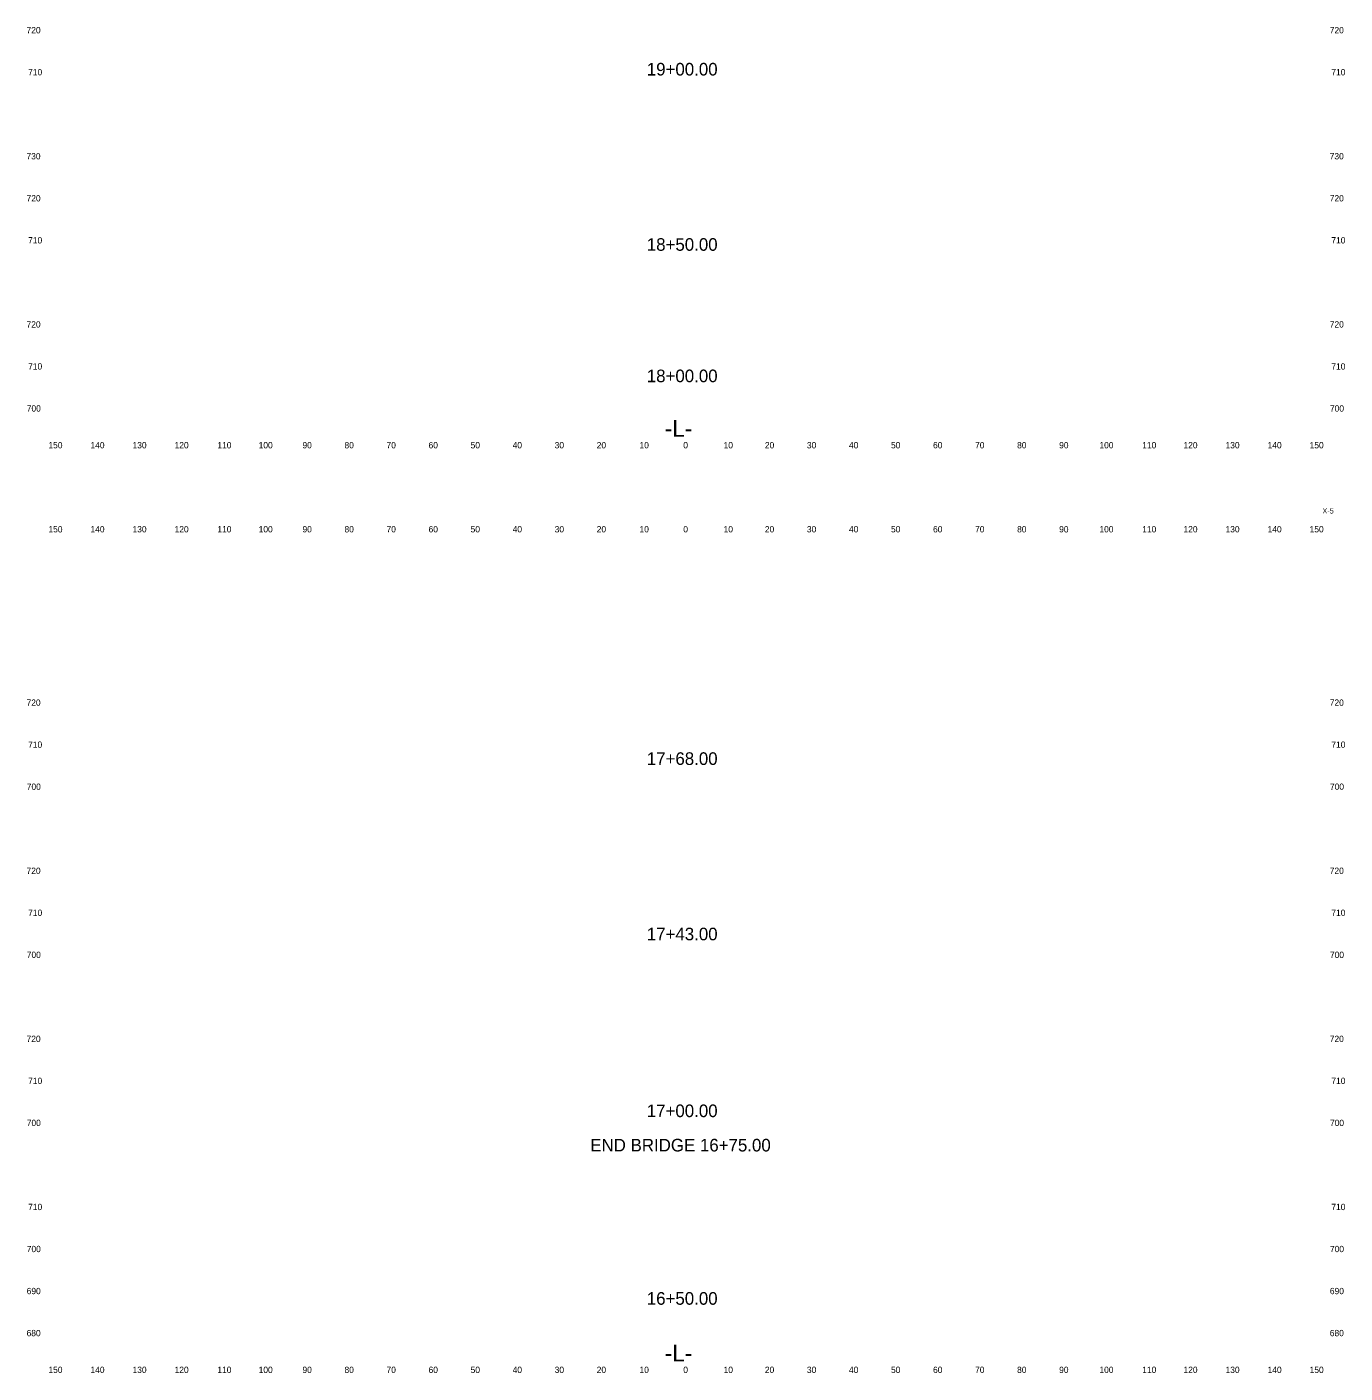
# Model space of a CAD drawing. Extents: x 3 to 317, y 1 to 1307.
# Drawn here: x 3.3 to 316.9, y 661.2 to 981.5 of the extents above; entities that cross this region are included whole.
import ezdxf

# ---------------------------------------------------------------- set-up
doc = ezdxf.new("R2010")
doc.units = 0
for name, color, linetype in [('Prop XS Alignment Label', 7, 'Continuous'), ('Prop XS Elevation Labels', 7, 'Continuous'), ('Prop XS Offset Labels', 7, 'Continuous'), ('Prop XS Sheet Number', 7, 'Continuous'), ('Prop XS Station Labels', 7, 'Continuous')]:
    doc.layers.add(name, color=color, linetype=linetype)

msp = doc.modelspace()

# ---------------------------------------------------------------- texts
at = {"layer": 'Prop XS Alignment Label'}
for p in [(155.06, 884), (155.06, 664)]:
    msp.add_text('-L-', height=4, dxfattribs=at).set_placement(p)
at = {"layer": 'Prop XS Elevation Labels'}
for s, p in [('720', (3.23, 980)), ('720', (313.23, 980)), ('710', (3.61, 970)), ('710', (313.61, 970)), ('730', (3.22, 950)), ('730', (313.22, 950)), ('720', (3.23, 940)), ('720', (313.23, 940)), ('710', (3.61, 930)), ('710', (313.61, 930)), ('720', (3.23, 910)), ('720', (313.23, 910)), ('710', (3.61, 900)), ('710', (313.61, 900)), ('700', (3.28, 890)), ('700', (313.28, 890)), ('720', (3.23, 820)), ('720', (313.23, 820)), ('710', (3.61, 810)), ('710', (313.61, 810)), ('700', (3.28, 800)), ('700', (313.28, 800)), ('720', (3.23, 780)), ('720', (313.23, 780)), ('710', (3.61, 770)), ('710', (313.61, 770)), ('700', (3.28, 760)), ('700', (313.28, 760)), ('720', (3.23, 740)), ('720', (313.23, 740)), ('710', (3.61, 730)), ('710', (313.61, 730)), ('700', (3.28, 720)), ('700', (313.28, 720)), ('710', (3.61, 700)), ('710', (313.61, 700)), ('700', (3.28, 690)), ('700', (313.28, 690)), ('690', (3.26, 680)), ('690', (313.26, 680)), ('680', (3.24, 670)), ('680', (313.24, 670))]:
    msp.add_text(s, height=1.5, dxfattribs=at).set_placement(p)
at = {"layer": 'Prop XS Offset Labels'}
for s, p in [('150', (8.44, 881.25)), ('140', (18.44, 881.25)), ('130', (28.44, 881.25)), ('120', (38.44, 881.25)), ('110', (48.62, 881.25)), ('100', (58.44, 881.25)), ('90', (68.86, 881.25)), ('80', (78.86, 881.25)), ('70', (88.86, 881.25)), ('60', (98.86, 881.25)), ('50', (108.86, 881.25)), ('40', (118.86, 881.25)), ('30', (128.86, 881.25)), ('20', (138.86, 881.25)), ('10', (149.04, 881.25)), ('0', (159.45, 881.25)), ('0', (159.45, 881.25)), ('10', (169.04, 881.25)), ('20', (178.86, 881.25)), ('30', (188.86, 881.25)), ('40', (198.86, 881.25)), ('50', (208.86, 881.25)), ('60', (218.86, 881.25)), ('70', (228.86, 881.25)), ('80', (238.86, 881.25)), ('90', (248.86, 881.25)), ('100', (258.44, 881.25)), ('110', (268.62, 881.25)), ('120', (278.44, 881.25)), ('130', (288.44, 881.25)), ('140', (298.44, 881.25)), ('150', (308.44, 881.25)), ('150', (8.44, 861.25)), ('140', (18.44, 861.25)), ('130', (28.44, 861.25)), ('120', (38.44, 861.25)), ('110', (48.62, 861.25)), ('100', (58.44, 861.25)), ('90', (68.86, 861.25)), ('80', (78.86, 861.25)), ('70', (88.86, 861.25)), ('60', (98.86, 861.25)), ('50', (108.86, 861.25)), ('40', (118.86, 861.25)), ('30', (128.86, 861.25)), ('20', (138.86, 861.25)), ('10', (149.04, 861.25)), ('0', (159.45, 861.25)), ('0', (159.45, 861.25)), ('10', (169.04, 861.25)), ('20', (178.86, 861.25)), ('30', (188.86, 861.25)), ('40', (198.86, 861.25)), ('50', (208.86, 861.25)), ('60', (218.86, 861.25)), ('70', (228.86, 861.25)), ('80', (238.86, 861.25)), ('90', (248.86, 861.25)), ('100', (258.44, 861.25)), ('110', (268.62, 861.25)), ('120', (278.44, 861.25)), ('130', (288.44, 861.25)), ('140', (298.44, 861.25)), ('150', (308.44, 861.25)), ('150', (8.44, 661.25)), ('140', (18.44, 661.25)), ('130', (28.44, 661.25)), ('120', (38.44, 661.25)), ('110', (48.62, 661.25)), ('100', (58.44, 661.25)), ('90', (68.86, 661.25)), ('80', (78.86, 661.25)), ('70', (88.86, 661.25)), ('60', (98.86, 661.25)), ('50', (108.86, 661.25)), ('40', (118.86, 661.25)), ('30', (128.86, 661.25)), ('20', (138.86, 661.25)), ('10', (149.04, 661.25)), ('0', (159.45, 661.25)), ('0', (159.45, 661.25)), ('10', (169.04, 661.25)), ('20', (178.86, 661.25)), ('30', (188.86, 661.25)), ('40', (198.86, 661.25)), ('50', (208.86, 661.25)), ('60', (218.86, 661.25)), ('70', (228.86, 661.25)), ('80', (238.86, 661.25)), ('90', (248.86, 661.25)), ('100', (258.44, 661.25)), ('110', (268.62, 661.25)), ('120', (278.44, 661.25)), ('130', (288.44, 661.25)), ('140', (298.44, 661.25)), ('150', (308.44, 661.25))]:
    msp.add_text(s, height=1.5, dxfattribs=at).set_placement(p)
at = {"layer": 'Prop XS Sheet Number'}
msp.add_text('X-5', height=1.25, dxfattribs=at).set_placement((311.5, 865.75))
at = {"layer": 'Prop XS Station Labels'}
for s, p in [('19+00.00', (150.77, 969.96)), ('18+50.00', (150.77, 928.26)), ('18+00.00', (150.77, 896.99)), ('17+68.00', (150.77, 805.93)), ('17+43.00', (150.77, 764.2)), ('17+00.00', (150.77, 722.13)), ('END BRIDGE 16+75.00', (137.33, 713.96)), ('16+50.00', (150.77, 677.49))]:
    msp.add_text(s, height=3, dxfattribs=at).set_placement(p)

doc.saveas('drawing.dxf')
